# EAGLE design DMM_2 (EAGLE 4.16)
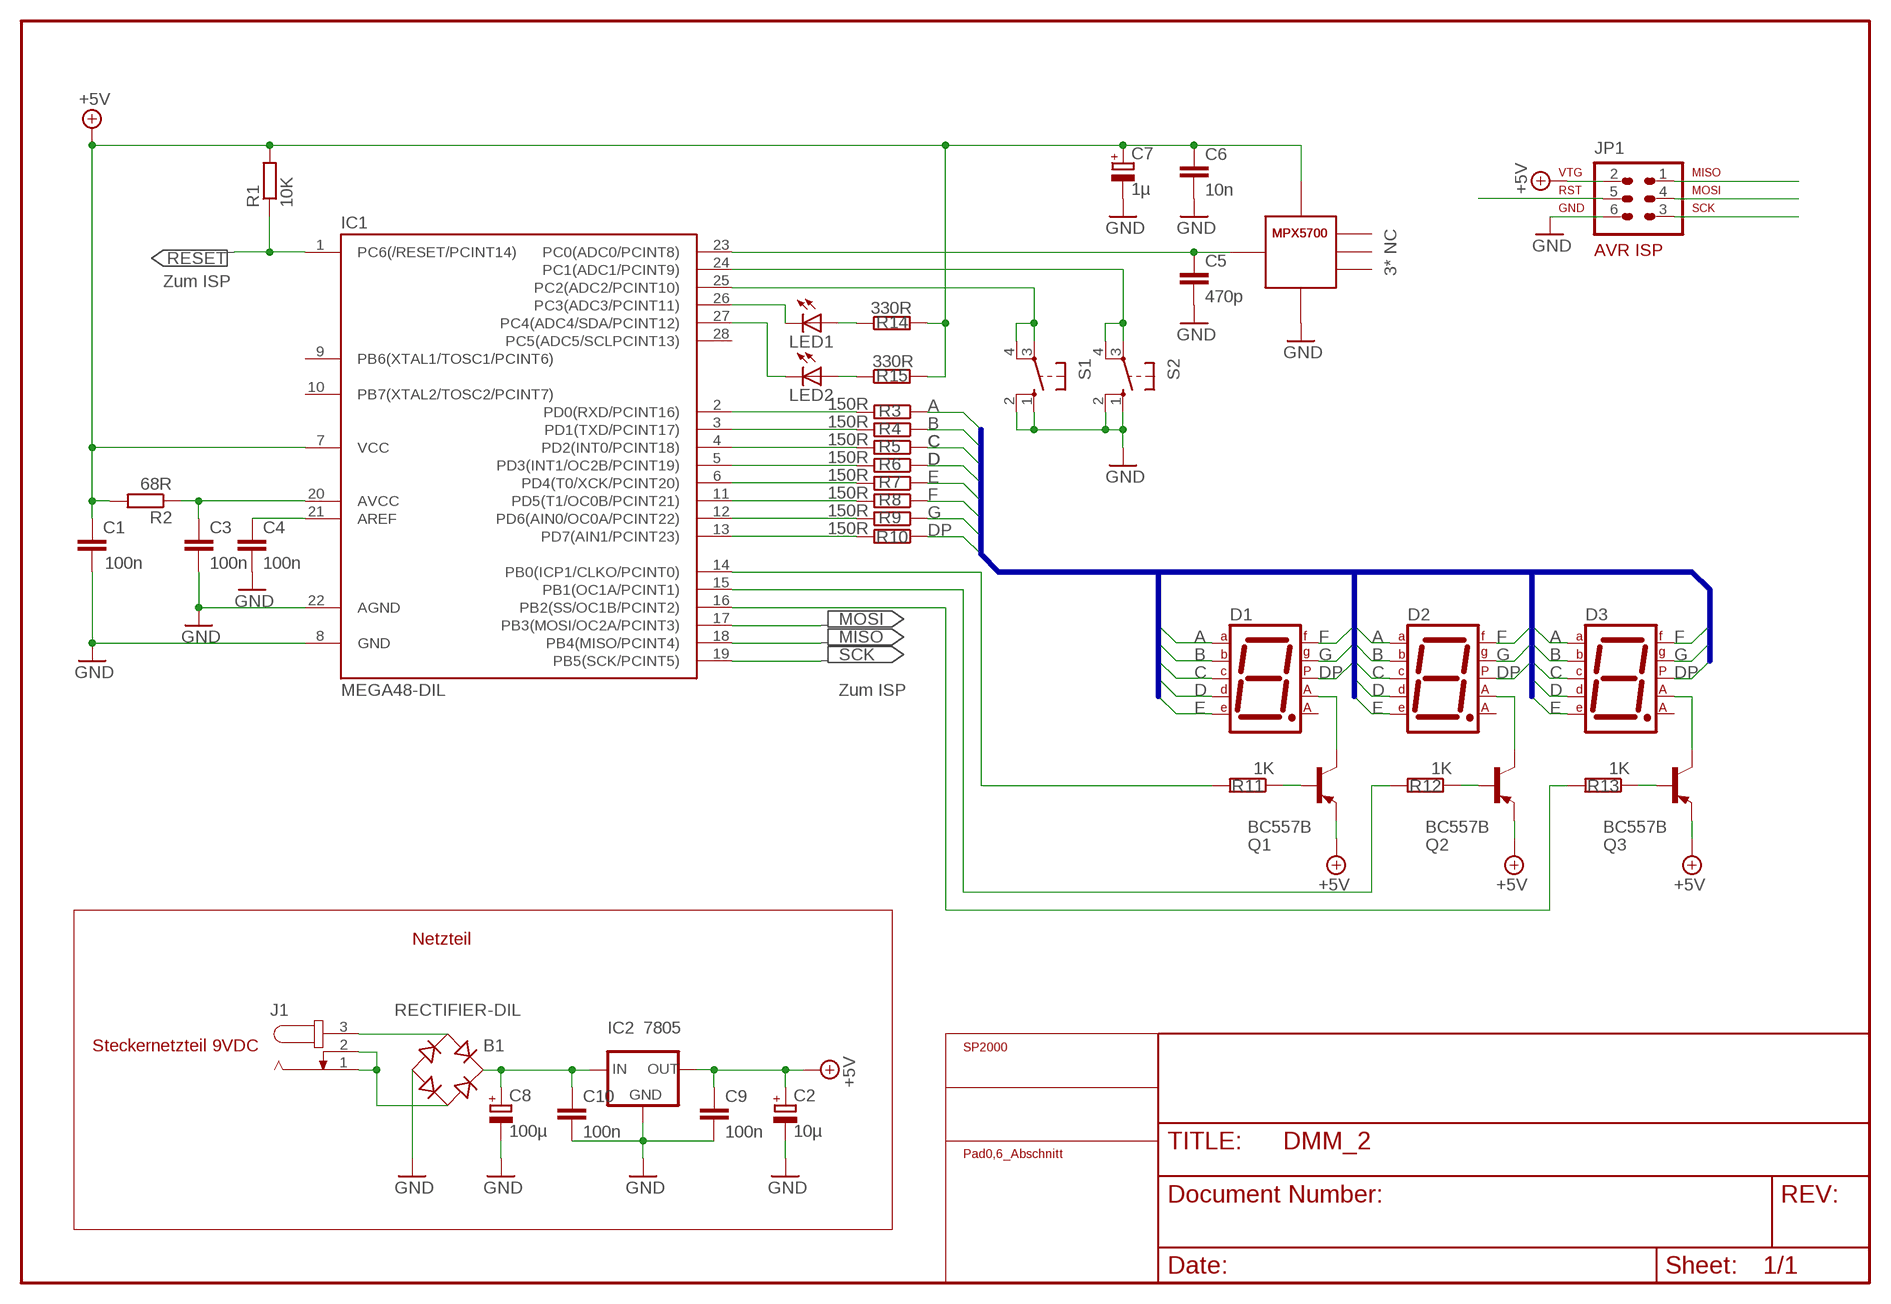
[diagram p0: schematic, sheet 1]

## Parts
B1  RECTIFIER-DIL  [B-DIL]
C1  100n  C-EU025-025X050  [C025-025X050]
C2  10µ  CPOL-EUE3.5-8  [E3,5-8]
C3  100n  C-EU025-025X050  [C025-025X050]
C4  100n  C-EU025-025X050  [C025-025X050]
C5  470p  C-EU025-025X050  [C025-025X050]
C6  10n  C-EU025-025X050  [C025-025X050]
C7  1µ  CPOL-EUE3.5-8  [E3,5-8]
C8  100µ  CPOL-EUE3.5-8  [E3,5-8]
C9  100n  C-EU025-025X050  [C025-025X050]
C10  100n  C-EU025-025X050  [C025-025X050]
D1  7SEG-CA  [7SEG-13]
D2  7SEG-CA  [7SEG-13]
D3  7SEG-CA  [7SEG-13]
GS1  MPX5700GS  [MPX5700GS]
IC1  MEGA48-DIL  MEGA48/88/168-PU  [DIL28-3]
IC2  7805  78XXL  [78XXL]
J1  JACK-PLUG1  [SPC4078]
JP1  AVR-ISP-6  [AVR-ISP-6]
LED1  LED3MM  [LED3MM]
LED2  LED3MM  [LED3MM]
Q1  BC557B  [TO92-EBC]
Q2  BC557B  [TO92-EBC]
Q3  BC557B  [TO92-EBC]
R1  10K  R-EU_0207/7  [0207/7]
R2  68R  R-EU_0207/7  [0207/7]
R3  150R  R-EU_0207/7  [0207/7]
R4  150R  R-EU_0207/7  [0207/7]
R5  150R  R-EU_0207/7  [0207/7]
R6  150R  R-EU_0207/7  [0207/7]
R7  150R  R-EU_0207/7  [0207/7]
R8  150R  R-EU_0207/7  [0207/7]
R9  150R  R-EU_0207/7  [0207/7]
R10  150R  R-EU_0207/7  [0207/7]
R11  1K  R-EU_0207/7  [0207/7]
R12  1K  R-EU_0207/7  [0207/7]
R13  1K  R-EU_0207/7  [0207/7]
R14  330R  R-EU_0207/7  [0207/7]
R15  330R  R-EU_0207/7  [0207/7]
S1  10-XX  [B3F-10XX]
S2  10-XX  [B3F-10XX]
U$1  SP2000  [SP2000]
U$2  PAD  [PAD0,6]
U$13  PAD_ABSCHNITT  [PAD0,6_ABSCHNITT]

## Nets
+5V: C1.1 C2.+ C6.1 C7.+ C9.1 GS1.VCC IC1.7(VCC) IC2.OUT JP1.2 Q1.E Q2.E Q3.E R1.2 R2.2 R14.2 R15.2
A: D1.7(A) D2.7(A) D3.7(A) R3.1
B: D1.6(B) D2.6(B) D3.6(B) R4.1
C: D1.4(C) D2.4(C) D3.4(C) R5.1
D: D1.2(D) D2.2(D) D3.2(D) R6.1
DP: D1.5(DP) D2.5(DP) D3.5(DP) R10.1
E: D1.1(E) D2.1(E) D3.1(E) R7.1
F: D1.9(F) D2.9(F) D3.9(F) R8.1
G: D1.10(G) D2.10(G) D3.10(G) R9.1
GND: B1.- C1.2 C2.- C3.2 C4.2 C5.2 C6.2 C7.- C8.- C9.2 C10.2 GS1.GND IC1.8(GND) IC1.22(AGND) IC2.GND JP1.6 S1.1(S) S1.2(S1) S2.1(S) S2.2(S1)
MISO: IC1.18(PB4(MISO/PCINT4)) JP1.1
MOSI: IC1.17(PB3(MOSI/OC2A/PCINT3)) JP1.4
N$1: C3.1 IC1.20(AVCC) R2.1
N$2: B1.AC1 J1.3
N$3: C5.1 GS1.OUT IC1.23(PC0(ADC0/PCINT8))
N$4: C4.1 IC1.21(AREF)
N$5: IC1.24(PC1(ADC1/PCINT9)) S2.3(P) S2.4(P1)
N$6: D2.3(CA1) Q2.C
N$7: IC1.2(PD0(RXD/PCINT16)) R3.2
N$8: IC1.3(PD1(TXD/PCINT17)) R4.2
N$9: IC1.4(PD2(INT0/PCINT18)) R5.2
N$10: IC1.5(PD3(INT1/OC2B/PCINT19)) R6.2
N$11: IC1.6(PD4(T0/XCK/PCINT20)) R7.2
N$12: IC1.11(PD5(T1/OC0B/PCINT21)) R8.2
N$13: IC1.12(PD6(AIN0/OC0A/PCINT22)) R9.2
N$14: IC1.13(PD7(AIN1/PCINT23)) R10.2
N$15: IC1.15(PB1(OC1A/PCINT1)) R12.2
N$16: D1.3(CA1) Q1.C
N$17: D3.3(CA1) Q3.C
N$18: B1.+ C8.+ C10.1 IC2.IN
N$19: Q1.B R11.1
N$20: Q2.B R12.1
N$22: IC1.14(PB0(ICP1/CLKO/PCINT0)) R11.2
N$23: IC1.16(PB2(SS/OC1B/PCINT2)) R13.2
N$24: IC1.25(PC2(ADC2/PCINT10)) S1.3(P) S1.4(P1)
N$25: IC1.26(PC3(ADC3/PCINT11)) LED1.K(C)
N$26: LED1.A R14.1
N$27: LED2.A R15.1
N$28: IC1.27(PC4(ADC4/SDA/PCINT12)) LED2.K(C)
N$30: B1.AC2 J1.1 J1.2
RESET: IC1.1(PC6(/RESET/PCINT14)) JP1.5 R1.1
SCK: IC1.19(PB5(SCK/PCINT5)) JP1.3
X: Q3.B R13.1
Unconnected: D1.8(CA2) D2.8(CA2) D3.8(CA2) GS1.NC1(N1) GS1.NC2(N2) GS1.NC3(N3) IC1.9(PB6(XTAL1/TOSC1/PCINT6)) IC1.10(PB7(XTAL2/TOSC2/PCINT7)) IC1.28(PC5(ADC5/SCLPCINT13))

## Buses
SEG:A,B,C,D,E,F,G,DP

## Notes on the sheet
- 3* NC
- Zum ISP
- Zum ISP
- Netzteil
- Steckernetzteil 9VDC

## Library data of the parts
B1 = rectifier:RECTIFIER-: Rectifier
C1 C3-C6 C9 C10 = rcl:C-EU: CAPACITOR, European symbol
C2 C7 C8 = rcl:CPOL-EU: POLARIZED CAPACITOR, European symbol
D1-D3 = special:7SEG-CA: 7-segment DISPLAY single anode, 13 mm
GS1 = mpx:MPX5700GS: Für liegende Montage. Die Pins müssen 90^Grad nach unten gebogen werden.
IC1 = avr-5-4.16:MEGA48/88/168-PU
IC2 = v-reg:78XXL: VOLTAGE REGULATOR
J1 = con-jack:JACK-PLUG: DC POWER JACK Power Jack, DC, Right Angle, Through Hole, Rated 5A at 16VDC, PC Terminals Distributor: Farnell (www.Farnell.de) Drawing: 84N1161.pdf / 84N1162.pdf Manufacturer: SPC Technology (www.spctechnology.com) Type: SPC4077 / SPC 4078
JP1 = atmel (2):AVR-ISP-6: AVR ISP-6 Serial Programming Header
LED1 LED2 = led:LED: LED
Q1-Q3 = transistor-pnp:BC557*: PNP Transistror
R1-R15 = rcl:R-EU_: RESISTOR, European symbol
S1 S2 = switch-omron:10-XX: OMRON SWITCH
U$1 = 0_Gehäuse_:SP2000
U$2 = 1_jmw:PAD
U$13 = 1_jmw:PAD_ABSCHNITT

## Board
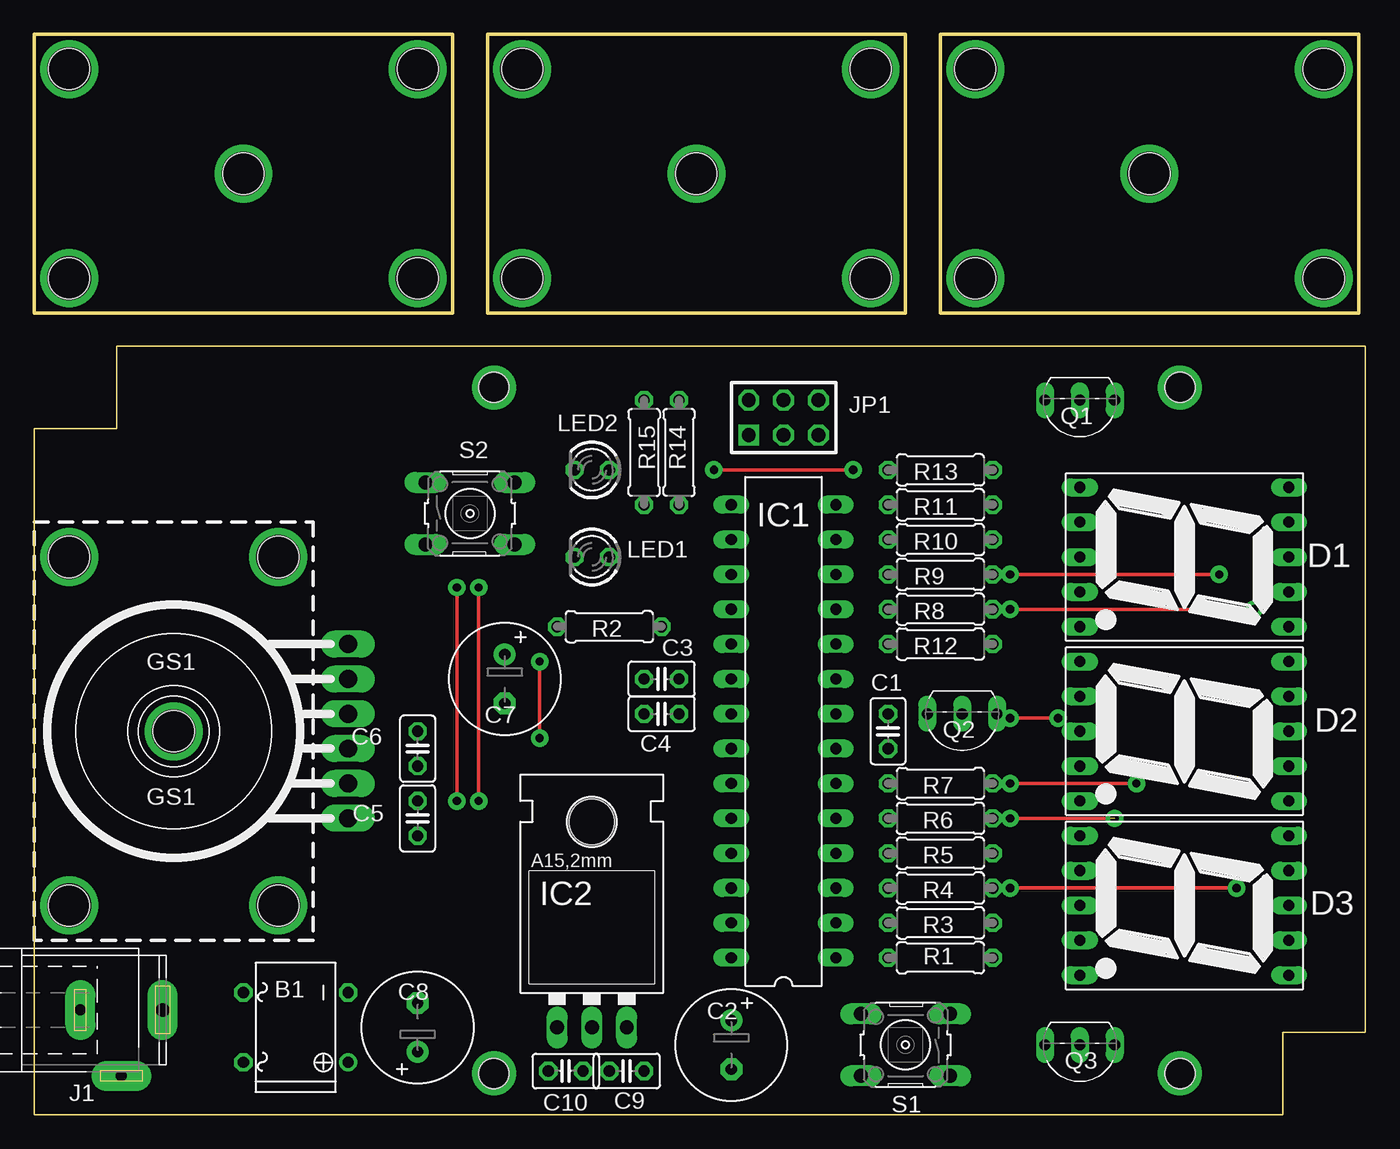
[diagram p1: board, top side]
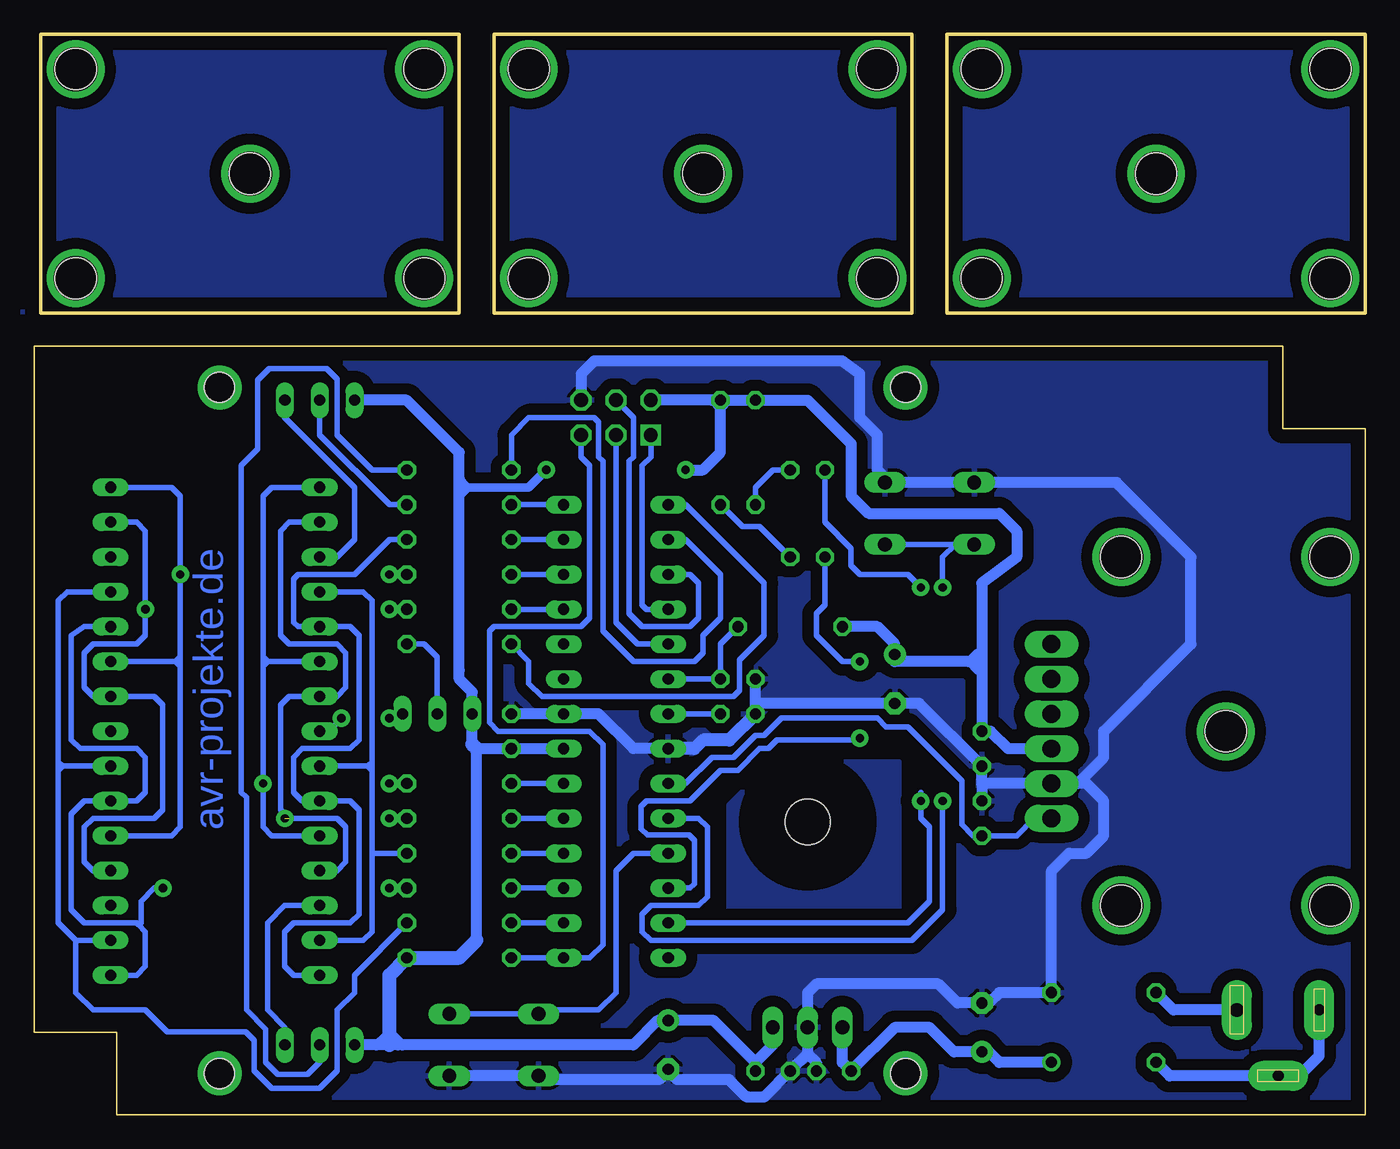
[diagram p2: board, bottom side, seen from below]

Size 97 x 78.74 mm. Coordinates in mm from the lower left corner, seen from the top.
Outline: 0,58.42 0,78.74 30.48,78.74 30.48,58.42 0,58.42
Outline: 33.02,58.42 33.02,78.74 63.5,78.74 63.5,58.42 33.02,58.42
Outline: 66.04,58.42 66.04,78.74 96.52,78.74 96.52,58.42 66.04,58.42
Copper layers (1*16): Top 0.035mm / dielectric 1.5mm / Bottom 0.035mm
Design rules "default": minimum track width 10mil, minimum drill 24mil, track to track 8mil, track to pad 8mil, pad to pad 8mil, via to via 8mil, smd to smd 8mil, copper to edge 40mil, drill to drill 8mil, minimum pad ring 10mil, minimum via ring 8mil, stop-mask expansion 4mil, vias tented up to drill 0mil, thermal gap 10mil
Holes 3 mm at 2.54,40.64 17.78,40.64 10.16,27.94 17.78,15.24 2.54,15.24 2.54,60.96 2.54,76.2 27.94,76.2 27.94,60.96 15.24,68.58 35.56,60.96 35.56,76.2 60.96,76.2 60.96,60.96 48.26,68.58 68.58,60.96 68.58,76.2 93.98,76.2 93.98,60.96 81.28,68.58

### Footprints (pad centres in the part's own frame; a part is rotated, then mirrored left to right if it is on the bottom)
B-DIL = drill 0.813 round: + -2.54,-3.81 | drill 0.813 octagon: - 2.54,-3.81; AC1 2.54,3.81; AC2 -2.54,3.81
C025-025X050 = drill 0.813 octagon: 1 -1.27,0; 2 1.27,0
E3,5-8 = drill 0.813 pad 1.6 round: + -1.778,0 | drill 0.813 pad 1.6 octagon: - 1.778,0
7SEG-13 = drill 0.813 long: 1 -5.08,-7.62; 2 -2.54,-7.62; 3 0,-7.62; 4 2.54,-7.62; 5 5.08,-7.62; 6 5.08,7.62; 7 2.54,7.62; 8 0,7.62; 9 -2.54,7.62; 10 -5.08,7.62
MPX5700GS = drill 1.3 long: GND -3.81,-12.7; NC1 1.27,-12.7; NC2 3.81,-12.7; NC3 6.35,-12.7; OUT -6.35,-12.7; VCC -1.27,-12.7
DIL28-3 = drill 0.813 long: 1 -16.51,-3.81; 2 -13.97,-3.81; 3 -11.43,-3.81; 4 -8.89,-3.81; 5 -6.35,-3.81; 6 -3.81,-3.81; 7 -1.27,-3.81; 8 1.27,-3.81; 9 3.81,-3.81; 10 6.35,-3.81; 11 8.89,-3.81; 12 11.43,-3.81; 13 13.97,-3.81; 14 16.51,-3.81; 15 16.51,3.81; 16 13.97,3.81; 17 11.43,3.81; 18 8.89,3.81; 19 6.35,3.81; 20 3.81,3.81; 21 1.27,3.81; 22 -1.27,3.81; 23 -3.81,3.81; 24 -6.35,3.81; 25 -8.89,3.81; 26 -11.43,3.81; 27 -13.97,3.81; 28 -16.51,3.81
78XXL = drill 1.016 long: GND 0,-3.81; IN -2.54,-3.81; OUT 2.54,-3.81 | hole 3.302: 0,11.176
SPC4078 = drill 0.8 pad 2.184 long: 1 -3,0; 2 0,-4.8 | drill 1 pad 2.184 long: 3 3,0
AVR-ISP-6 = drill 1.016 square: 1 -2.54,-1.27 | drill 1.016 octagon: 2 -2.54,1.27; 3 0,-1.27; 4 0,1.27; 5 2.54,-1.27; 6 2.54,1.27
LED3MM = drill 0.813 octagon: A -1.27,0; K 1.27,0
TO92-EBC = drill 0.813 long: B 0,-1.27; C -2.54,-1.27; E 2.54,-1.27
0207/7 = drill 0.813 octagon: 1 -3.81,0; 2 3.81,0
B3F-10XX = drill 1.016 long: 1 -3.251,2.261; 2 3.251,2.261; 3 -3.251,-2.261; 4 3.251,-2.261
SP2000 = drill 2.184 round: P$1 33.5,53; P$2 83.5,53; P$3 83.5,3; P$4 33.5,3 | hole 2.184: 33.5,53; 83.5,53; 83.5,3; 33.5,3

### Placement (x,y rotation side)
B1  19.05,6.35 90 top
C1  62.23,27.94 90 top
C2  50.8,5.08 270 top
C3  45.72,31.75 180 top
C4  45.72,29.21 180 top
C5  27.94,21.59 90 top
C6  27.94,26.67 270 top
C7  34.29,31.75 270 top
C8  27.94,6.35 90 top
C9  43.18,3.17 180 top
C10  38.73,3.17 0 top
D1  83.82,40.64 270 top
D2  83.82,27.94 270 top
D3  83.82,15.24 270 top
GS1  10.16,27.94 90 top
IC1  54.61,27.94 90 top
IC2  40.64,10.16 0 top
J1  6.35,7.62 0 top
JP1  54.61,50.8 0 top
LED1  40.64,40.64 180 top
LED2  40.64,46.99 180 top
Q1  76.2,50.8 180 top
Q2  67.63,27.94 180 top
Q3  76.2,3.81 180 top
R1  66.04,11.43 0 top
R2  41.91,35.56 180 top
R3  66.04,13.97 180 top
R4  66.04,16.51 180 top
R5  66.04,19.05 180 top
R6  66.04,21.59 180 top
R7  66.04,24.13 180 top
R8  66.04,36.83 180 top
R9  66.04,39.37 180 top
R10  66.04,41.91 180 top
R11  66.04,44.45 180 top
R12  66.04,34.29 180 top
R13  66.04,46.99 180 top
R14  46.99,48.26 90 top
R15  44.45,48.26 90 top
S1  63.5,5.08 180 top
S2  31.75,43.81 0 top
U$1  0,0 0 top
U$2  69.85,39.37 0 top
U$3  PAD  [PAD0,6]  69.85,46.99 0 top
U$4  PAD  [PAD0,6]  69.85,44.45 0 top
U$5  PAD  [PAD0,6]  69.85,41.91 0 top
U$6  PAD  [PAD0,6]  69.85,36.83 0 top
U$7  PAD  [PAD0,6]  62.23,41.91 0 top
U$8  PAD_ABSCHNITT  [PAD0,6_ABSCHNITT]  62.23,46.99 90 top
U$9  PAD_ABSCHNITT  [PAD0,6_ABSCHNITT]  62.23,44.45 270 top
U$10  PAD  [PAD0,6]  69.85,34.29 0 top
U$11  PAD  [PAD0,6]  62.23,39.37 0 top
U$12  PAD_ABSCHNITT  [PAD0,6_ABSCHNITT]  44.45,31.75 180 top
U$13  62.23,34.29 270 top
U$14  PAD_ABSCHNITT  [PAD0,6_ABSCHNITT]  62.23,36.83 90 top
U$15  PAD_ABSCHNITT  [PAD0,6_ABSCHNITT]  62.23,29.21 90 top
U$16  PAD_ABSCHNITT  [PAD0,6_ABSCHNITT]  62.23,26.67 270 top
U$17  PAD_ABSCHNITT  [PAD0,6_ABSCHNITT]  71.12,28.89 180 top
U$18  PAD_ABSCHNITT  [PAD0,6_ABSCHNITT]  71.12,24.13 180 top
U$19  PAD_ABSCHNITT  [PAD0,6_ABSCHNITT]  71.12,21.59 180 top
U$20  PAD_ABSCHNITT  [PAD0,6_ABSCHNITT]  80.33,24.13 0 top
U$21  PAD  [PAD0,6]  69.85,24.13 0 top
U$22  PAD  [PAD0,6]  69.85,21.59 0 top
U$23  PAD  [PAD0,6]  69.85,19.05 0 top
U$24  PAD  [PAD0,6]  62.23,24.13 0 top
U$25  PAD  [PAD0,6]  62.23,21.59 0 top
U$26  PAD  [PAD0,6]  62.23,19.05 0 top
U$27  PAD  [PAD0,6]  62.23,16.51 0 top
U$28  PAD  [PAD0,6]  69.85,16.51 0 top
U$29  PAD  [PAD0,6]  69.85,13.97 0 top
U$30  PAD  [PAD0,6]  68.58,11.43 0 top
U$31  PAD  [PAD0,6]  62.23,11.43 0 top
U$34  PAD  [PAD0,6]  69.85,11.43 0 top
U$35  PAD  [PAD0,6]  87.63,16.51 0 top
U$36  PAD  [PAD0,6]  88.9,36.83 0 top
U$37  PAD  [PAD0,6]  86.36,39.37 0 top
U$38  PAD  [PAD0,6]  71.12,39.37 0 top
U$39  PAD_ABSCHNITT  [PAD0,6_ABSCHNITT]  74.61,28.89 0 top
U$40  PAD_ABSCHNITT  [PAD0,6_ABSCHNITT]  71.12,36.83 180 top
U$42  PAD  [PAD0,6]  44.45,29.21 0 top
U$43  PAD  [PAD0,6]  78.74,21.59 0 top
U$44  PAD  [PAD0,6]  41.91,40.64 0 top
U$45  PAD  [PAD0,6]  39.37,40.64 0 top
U$46  PAD  [PAD0,6]  39.37,46.99 0 top
U$47  PAD  [PAD0,6]  41.91,46.99 0 top
U$48  PAD  [PAD0,6]  44.45,52.07 0 top
U$49  PAD  [PAD0,6]  46.99,52.07 0 top
U$50  PAD_ABSCHNITT  [PAD0,6_ABSCHNITT]  57.15,52.07 90 top
U$51  PAD  [PAD0,6]  59.69,46.99 0 top
U$52  PAD  [PAD0,6]  46.99,44.45 0 top
U$53  PAD  [PAD0,6]  44.45,44.45 0 top
U$54  PAD  [PAD0,6]  45.72,35.56 0 top
U$55  PAD  [PAD0,6]  15.24,3.81 0 top
U$56  PAD  [PAD0,6]  15.24,8.89 0 top
U$57  PAD  [PAD0,6]  22.86,8.89 0 top
U$58  PAD  [PAD0,6]  22.86,3.81 0 top
U$59  PAD  [PAD0,6]  37.47,3.17 0 top
U$60  PAD  [PAD0,6]  40.01,3.17 0 top
U$61  PAD  [PAD0,6]  41.91,3.17 0 top
U$62  PAD  [PAD0,6]  44.45,3.17 0 top
U$63  PAD  [PAD0,6]  27.94,8.13 0 top
U$64  PAD  [PAD0,6]  27.94,4.57 0 top
U$65  PAD  [PAD0,6]  50.8,3.3 0 top
U$66  PAD  [PAD0,6]  50.8,6.86 0 top
U$67  PAD  [PAD0,6]  27.94,20.32 0 top
U$68  PAD  [PAD0,6]  27.94,22.86 0 top
U$69  PAD  [PAD0,6]  27.94,25.4 0 top
U$70  PAD  [PAD0,6]  27.94,27.94 0 top
U$71  PAD  [PAD0,6]  34.29,29.97 0 top
U$72  PAD  [PAD0,6]  34.29,33.53 0 top
U$73  PAD  [PAD0,6]  38.1,35.56 0 top
U$74  PAD  [PAD0,6]  36.83,33.02 0 top
U$75  PAD  [PAD0,6]  36.83,27.43 0 top
U$76  PAD_ABSCHNITT  [PAD0,6_ABSCHNITT]  32.38,38.42 0 top
U$77  PAD_ABSCHNITT  [PAD0,6_ABSCHNITT]  30.8,38.42 180 top
U$78  PAD_ABSCHNITT  [PAD0,6_ABSCHNITT]  32.38,22.86 0 top
U$79  PAD_ABSCHNITT  [PAD0,6_ABSCHNITT]  30.8,22.86 180 top
U$80  PAD_ABSCHNITT  [PAD0,6_ABSCHNITT]  46.99,31.75 90 top
U$81  PAD_ABSCHNITT  [PAD0,6_ABSCHNITT]  46.99,29.21 270 top
U$86  PAD  [PAD0,6]  54.61,52.07 0 top
U$87  PAD  [PAD0,6]  52.07,52.07 0 top

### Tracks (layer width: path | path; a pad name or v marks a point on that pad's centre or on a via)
+5V  (via drill 0.6 pad 1.27)
  Top 0.254: v59.69,46.99 v49.53,46.99
  Bottom 0.61: v59.69,46.99 60.96,45.72 65.41,45.72 | 66.04,45.72 65.41,45.72 | 65.41,45.72 66.04,46.35 | 66.04,45.09 65.41,45.72 | 46.35,52.07 46.99,51.44 47.62,52.07 | 28.26,33.66 28.89,33.02 28.26,32.38 | 70.48,5.08 71.12,5.71 71.44,5.71 72.07,5.08 | 70.17,5.08 71.12,6.03
  Bottom 0.813: IC2.OUT 43.18,5.08 44.45,3.81 | C9.1 44.45,3.81 | 44.45,3.81 47.5,6.86 C2.+ 51.56,6.86 53.34,5.08 70.17,5.08 70.48,5.08 71.12,5.08 | 71.12,5.08 72.07,5.08 Q3.E | 71.12,5.08 71.12,5.71 71.12,6.03 | IC1.7 C1.1 64.77,26.67 64.77,12.7 | GS1.VCC 26.04,26.67 27.3,27.94 C6.1 27.94,33.02 | 34.29,33.02 C7.+ | 27.94,33.02 28.89,33.02 34.29,33.02 | Q1.E 69.85,52.07 66.04,48.26 66.04,46.35 66.04,45.72 66.04,45.09 66.04,32.38 66.04,31.75 65.09,30.8 Q2.E 65.09,26.99 | R14.2 46.35,52.07 R15.2 40.64,52.07 37.47,48.9 37.47,45.09 36.2,43.81 26.67,43.81 25.4,42.55 25.4,40.64 27.94,38.73 27.94,33.02 | R14.2 47.62,52.07 JP1.2 | R2.2 35.56,35.56 34.29,34.29 34.29,33.02 | R14.2 46.99,51.44 46.99,48.26 48.26,46.99 v49.53,46.99
  Bottom 1.016: 64.77,12.7 66.04,11.43 R1.2 71.12,10.16 71.12,5.08 | 64.77,26.67 65.09,26.99
A
  Bottom 0.406: 95.25,25.4 95.25,25.72 | 95.25,25.72 95.25,37.47 94.61,38.1 D1.7 | 95.25,25.4 94.93,25.4 | 94.93,25.4 D2.7 | 93.98,12.7 D3.7 | 93.98,12.7 95.25,13.97 95.25,25.08 | 95.25,25.08 95.25,25.4 | 94.93,25.4 95.25,25.72 | 95.25,25.08 94.93,25.4 | R3.1 73.66,10.16 73.66,8.89 74.93,7.62 74.93,3.17 76.2,1.91 79.69,1.91 80.96,3.17 80.96,5.4 81.6,6.03 87.31,6.03 88.9,7.62 92.71,7.62 93.98,8.89 93.98,12.7
B  (via drill 0.6 pad 1.27)
  Top 0.254: v71.12,16.51 v87.63,16.51
  Bottom 0.406: D1.6 93.34,35.56 94.3,34.92 94.3,27.3 93.66,26.67 89.53,26.67 88.9,26.04 88.9,23.5 89.53,22.86 D2.6 93.34,22.86 94.3,21.91 94.3,14.92 93.34,13.97 89.53,13.97 89.38,13.81 | 89.38,13.81 88.9,13.34 88.9,10.79 89.53,10.16 D3.6 | R4.1 v71.12,16.51 | v87.63,16.51 88.27,16.51 89.22,15.56 89.22,13.97 89.38,13.81 | 89.38,13.81
C
  Bottom 0.406: 72.39,25.4 72.39,25.72 | 72.39,25.72 72.39,37.47 73.03,38.1 D1.4 | 72.39,25.4 72.71,25.4 | 72.71,25.4 D2.4 | 72.39,25.08 72.39,25.4 | 72.39,19.05 72.39,13.34 73.03,12.7 D3.4 | 72.39,19.05 72.39,25.08 | 72.71,25.4 72.39,25.72 | 72.39,25.08 72.71,25.4 | 72.39,19.05 R5.1
D  (via drill 0.6 pad 1.27)  (1 unrouted)
  Top 0.254: v71.12,21.59 v78.74,21.59
  Bottom 0.406: D1.2 78.42,43.18 79.06,42.55 79.06,34.92 78.42,34.29 74.93,34.29 74.3,33.66 74.3,31.11 74.93,30.48 D2.2 78.42,30.48 79.06,29.84 79.06,22.23 78.42,21.59 74.93,21.59 74.3,20.95 74.3,18.41 74.93,17.78 D3.2 | R6.1 v71.12,21.59
DP
  Bottom 0.406: D3.5 78.11,10.16 78.74,10.79 78.74,13.34 78.11,13.97 73.98,13.97 73.34,14.61 73.34,22.23 73.98,22.86 D2.5 77.47,22.86 78.11,23.5 78.11,26.04 77.47,26.67 73.98,26.67 73.34,27.3 73.34,34.92 73.98,35.56 D1.5 77.79,35.56 78.11,35.88 78.11,39.05 77.79,39.37 73.66,39.37 71.12,41.91 R10.1
E  (via drill 0.6 pad 1.27)
  Top 0.254: v71.12,24.13 v80.33,24.13
  Bottom 0.406: 80.33,33.02 80.33,33.34 | 80.33,33.34 80.33,45.09 79.69,45.72 D1.1 | D3.1 79.69,20.32 80.33,20.95 v80.33,24.13 80.33,32.7 | 80.33,32.7 80.33,33.02 | 80.33,33.02 80.01,33.02 | 80.01,33.02 D2.1 | 80.01,33.02 80.33,33.34 | 80.33,32.7 80.01,33.02 | R7.1 v71.12,24.13
F  (via drill 0.6 pad 1.27)
  Top 0.254: v71.12,36.83 v88.9,36.83
  Bottom 0.406: D1.9 89.53,43.18 88.9,42.55 v88.9,36.83 88.9,34.92 89.53,34.29 92.71,34.29 93.34,33.66 93.34,31.11 92.71,30.48 D2.9 88.27,30.48 87.63,29.84 87.63,22.23 88.27,21.59 92.71,21.59 93.34,20.95 93.34,18.41 92.71,17.78 D3.9 | R8.1 v71.12,36.83
G  (via drill 0.6 pad 1.27)
  Top 0.254: v71.12,39.37 v86.36,39.37
  Bottom 0.406: 86.36,33.34 86.36,33.02 | 86.36,33.34 v86.36,39.37 86.36,45.09 87,45.72 D1.10 | 86.36,33.02 86.36,32.7 | 86.36,32.7 86.36,20.95 87,20.32 D3.10 | 86.36,33.02 86.68,33.02 | 86.68,33.02 D2.10 | 86.36,33.34 86.36,32.7 | 86.36,32.7 86.68,33.02 | 86.36,33.34 86.68,33.02 | R9.1 v71.12,39.37
GND
  Bottom 0.813: JP1.6 57.15,53.98 56.2,54.93 38.1,54.93 36.83,53.98 36.83,50.8 35.56,49.53 35.56,46.99 34.92,46.35 35,46.28 S2.2 35,45.8 34.92,45.72 34.29,45.72 33.93,46.08 S2.1 18.14,46.08 12.7,40.64 12.7,34.29 19.05,27.94 19.05,26.04 20.95,24.13 | C1.2 IC1.8 55.88,29.21 53.34,26.67 IC1.22 | S1.1 59.97,2.82 59.69,2.54 | 59.69,2.54 60.96,2.54 | 59.69,2.54 51.44,2.54 50.8,3.17 | 50.8,3.17 C2.- | 50.8,3.17 50.16,2.54 46.35,2.54 45.09,1.27 43.81,1.27 C9.2 40.64,4.45 | 44.45,29.84 C4.2 | 44.45,29.84 C3.2 | 44.45,29.84 44.32,29.97 C7.- 32.51,29.97 C6.2 27.94,24.13 | C10.2 40.01,3.81 40.64,4.45 | 27.94,24.13 C5.2 | 40.64,4.45 IC2.GND 40.64,8.89 40.01,9.53 31.11,9.53 29.72,8.13 C8.- 27.43,8.13 26.67,8.89 B1.- 22.86,17.78 21.59,19.05 20.32,19.05 19.05,20.32 19.05,22.86 20.32,24.13 20.95,24.13 | 27.94,24.13 GS1.GND 20.95,24.13
  Bottom 0.942: IC1.22 48.9,26.67 48.26,27.3 46.35,27.3 C4.2
  pour Bottom (isolate 0.813): 0,0 97.16,0 97.16,55.88 0,55.88
MISO
  Bottom 0.406: JP1.1 52.07,47.94 52.7,47.31 52.7,37.15 52.39,36.83 IC1.18
MOSI
  Bottom 0.406: JP1.4 53.34,50.8 53.34,47.94 53.66,47.62 53.66,36.51 52.7,35.56 49.21,35.56 48.58,36.2 48.58,38.73 49.21,39.37 IC1.17
N$1
  Bottom 0.406: IC1.20 C3.1 46.99,34.29 R2.1
N$2
  Bottom 0.813: J1.3 13.97,7.62 B1.AC1
N$3
  Bottom 0.406: GS1.OUT 24.13,21.59 25.4,20.32 C5.1 28.57,20.32 29.4,21.14 29.4,24.32 33.34,28.26 34.92,28.26 35.56,28.89 42.55,28.89 43.81,27.62 44.45,27.62 46.04,26.04 47.62,26.04 49.53,24.13 IC1.23
N$4
  Bottom 0.406: C4.1 IC1.21
N$5  (via drill 0.6 pad 1.27)
  Top 0.254: v30.8,22.86 v30.8,38.42
  Bottom 0.406: S2.3 28.5,41.35 28.57,41.27 28.85,41.55 29.84,41.55 | 29.84,41.55 S2.4 35,41.35 34.92,41.27 36.2,41.27 | 29.84,41.55 29.84,41.59 30.8,40.64 v30.8,38.42 | v30.8,22.86 30.8,14.92 33.02,12.7 52.07,12.7 52.7,13.34 52.7,14.61 52.07,15.24 48.58,15.24 47.94,15.88 47.94,20.95 48.58,21.59 IC1.24
N$6  (via drill 0.6 pad 1.27)
  Top 0.254: v71.12,28.89 v74.61,28.89
  Bottom 0.406: D2.3 75.56,27.94 v74.61,28.89 | v71.12,28.89 70.17,28.89 69.85,29.21 Q2.C
N$7
  Bottom 0.406: IC1.2 R3.2
N$8
  Bottom 0.406: IC1.3 R4.2
N$9
  Bottom 0.406: IC1.4 R5.2
N$10
  Bottom 0.406: IC1.5 R6.2
N$11
  Bottom 0.406: IC1.6 R7.2
N$12
  Bottom 0.406: IC1.11 R8.2
N$13
  Bottom 0.406: IC1.12 R9.2
N$14
  Bottom 0.406: IC1.13 R10.2
N$15
  Bottom 0.406: IC1.15 49.53,44.45 43.81,38.73 43.81,34.92 45.59,33.15 45.59,32.77 45.59,30.92 46.04,30.48 60.01,30.48 60.96,31.43 60.96,33.02 R12.2
N$16
  Bottom 0.406: D1.3 74.93,40.64 73.66,41.91 73.66,45.72 78.74,50.8 Q1.C
N$17
  Bottom 0.406: D3.3 78.74,15.24 80.01,13.97 80.01,7.62 78.74,6.35 Q3.C
N$18
  Bottom 0.813: B1.+ 26.67,3.81 27.43,4.57 C8.+ 29.97,4.57 31.75,6.35 34.29,6.35 C10.1 38.1,3.81 IC2.IN
N$19
  Bottom 0.406: R11.1 71.12,44.45 76.2,49.53 Q1.B
N$20
  Bottom 0.406: Q2.B 67.63,33.34 68.58,34.29 R12.1
N$21
  pour Bottom (isolate 0.813): 0,78.74 96.52,78.74 97.79,58.42 -0.03,58.42
N$22
  Bottom 0.406: IC1.14 R11.2
N$23
  Bottom 0.406: IC1.16 49.53,41.91 46.99,39.37 46.99,36.2 48.26,34.92 48.26,33.66 48.9,33.02 53.34,33.02 55.56,35.24 55.56,47.62 55.88,47.94 55.88,50.48 56.2,50.8 60.96,50.8 62.23,49.53 R13.2
N$24
  Bottom 0.406: IC1.25 53.34,19.05 54.61,17.78 54.61,8.89 55.88,7.62 60.33,7.62 60.25,7.54 S1.4 66.32,7.34 66.67,6.99 66.75,7.06 S1.3
N$25  (via drill 0.6 pad 1.27)
  Top 0.254: v36.83,27.43 v36.83,33.02
  Bottom 0.406: v36.83,33.02 38.1,33.02 40.01,34.92 40.01,36.51 39.37,37.15 LED1.K | IC1.26 49.21,16.51 48.9,16.83 48.9,20 49.28,20.38 52.32,20.38 52.77,20.83 52.77,22.48 52.39,22.86 49.21,22.86 46.99,25.08 45.72,25.08 44.13,26.67 43.5,26.67 42.86,27.3 37.15,27.3 37.02,27.43 v36.83,27.43
N$26
  Bottom 0.406: R14.1 45.4,42.86 44.13,42.86 LED1.A
N$27
  Bottom 0.406: LED2.A 43.18,46.99 44.45,45.72 R15.1
N$28  (via drill 0.6 pad 1.27)
  Top 0.254: v32.38,22.86 v32.38,38.42
  Bottom 0.406: LED2.K 39.37,43.18 37.47,41.27 37.47,40.01 36.83,39.37 33.34,39.37 v32.38,38.42 | 32.38,23.5 v32.38,22.86 32.38,21.59 31.75,20.95 31.75,15.56 33.34,13.97 IC1.27
N$29
  pour Bottom (isolate 0.813): 33.97,25.72 43.18,25.72 46.35,22.54 46.35,14.92 33.97,14.92
N$30
  Bottom 0.813: J1.1 3.35,4.27 5.08,2.54 6.35,2.54 J1.2 14.25,2.82 B1.AC2
N$32  (via drill 3.2)
  other vias: 17.78,40.64
N$33  (via drill 3.2)
  other vias: 17.78,15.24
N$34  (via drill 3.2)
  other vias: 2.54,15.24
N$35  (via drill 3.2)
  other vias: 10.16,27.94
N$36  (via drill 3.2)
  other vias: 60.96,60.96
N$37  (via drill 3.2)
  other vias: 93.98,60.96
RESET
  Bottom 0.406: R1.1 IC1.1 56.52,11.43 55.56,12.38 55.56,26.99 56.52,27.94 63.18,27.94 63.82,28.57 63.82,35.24 63.5,35.56 57.15,35.56 56.52,36.2 56.52,47.31 57.15,47.94 JP1.5
S$2  (via drill 3.2)
  other vias: 2.54,40.64
S$3  (via drill 3.2)
  other vias: 2.54,60.96
S$4  (via drill 3.2)
  other vias: 15.24,68.58
S$5  (via drill 3.2)
  other vias: 27.94,76.2
S$6  (via drill 3.2)
  other vias: 2.54,76.2
S$7  (via drill 3.2)
  other vias: 27.94,60.96
S$8  (via drill 3.2)
  other vias: 35.56,60.96
S$9  (via drill 3.2)
  other vias: 35.56,76.2
S$10  (via drill 3.2)
  other vias: 60.96,76.2
S$11  (via drill 3.2)
  other vias: 48.26,68.58
S$12  (via drill 3.2)
  other vias: 68.58,60.96
S$13  (via drill 3.2)
  other vias: 68.58,76.2
S$14  (via drill 3.2)
  other vias: 93.98,76.2
S$15  (via drill 3.2)
  other vias: 81.28,68.58
SCK
  Bottom 0.406: JP1.3 54.61,35.88 53.02,34.29 IC1.19
X
  Bottom 0.406: R13.1 72.39,46.99 74.93,49.53 74.93,53.59 75.69,54.36 79.88,54.36 80.71,53.53 80.71,48.51 81.92,47.31 81.92,23.5 81.53,23.11 81.53,7.62 80.14,6.22 80.14,3.81 79.25,2.92 77.09,2.92 76.2,3.81 Q3.B

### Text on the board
Bottom: avr-projekte.de
Help: 10,75 | d=3mm | 11,75 | 19,0 | 6,75 | 14,95 | d=3mm | 18,10 | 30,75 | d=3mm | 34,50 | d=7mm | 43,35 | 12,85 | 40,0 | 30,75 | d=3mm | 10,75 | 7,85 | 36,25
